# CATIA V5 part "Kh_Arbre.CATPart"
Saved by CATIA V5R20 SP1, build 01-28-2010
Part number: Arbre
Bounding box of the stored display mesh (mm): x -110 to 84, y -15 to 15, z -15 to 15
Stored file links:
  G:\Khaled_CFAO_2011\SIL\SIL_GR1\tmerino\Khaled\CAD_Thinkmotion\Kh_Arbre.CATPart
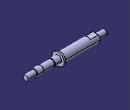
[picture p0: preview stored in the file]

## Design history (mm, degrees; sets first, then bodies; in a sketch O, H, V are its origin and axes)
Body1 (main body)
  Sketch1 on yz-plane, origin (0, 0, 0), H (0, 1, 0), V (0, 0, 1)
    circle A1 centre (0, 0) radius 15
    radius A1 = 15
  Pad1: profile Sketch1, direction (1, 0, 0), length 4
  Sketch2 on end face of Pad1, origin (4, 0, 0), H (0, 1, 0), V (0, 0, 1)
  Sketch3 on start face of Pad1, origin (0, 0, 0), H (0, -1, 0), V (0, 0, 1)
    circle A1 centre (0, 0) radius 11
    radius A1 = 11
  Pad2: profile Sketch3, direction (-1, 0, 0), length 88
  Sketch4 on end face of Pad2, origin (-88, 0, 0), H (0, -1, 0), V (0, 0, 1)
    circle A1 centre (0, 0) radius 6
    radius A1 = 6
  Pad3: profile Sketch4, direction (-1, 0, 0), length 22
  Sketch5 on zx-plane, origin (0, 0, 0), H (-1, 0, 0), V (0, 0, 1)
    line L1 (68, 20) -> (88, 20)
    line L2 (88, 20) -> (88, 8.5)
    line L3 (88, 8.5) -> (68, 8.5)
    line L4 (68, 8.5) -> (68, 20)
    reference projected line E1 (88, 11) -> (88, -11) from edge [face of Pad2 from Sketch3.A1 | end face of Pad2]
    reference projected line E2 through (0, 0) direction (1, 0) from axis of face of Pad2 from Sketch3.A1
    distance E1 L2 = 0
    distance L2 L4 = 20
    distance E2 L3 = 8.5
    horizontal: L1 H, L3 H
    vertical: L2 V, L4 V
  Pocket1: profile Sketch5, direction (0, 1, 0), length 22, opposite side length 22
  Sketch6 on end face of Pad1, origin (4, 0, 0), H (0, 1, 0), V (0, 0, 1)
    circle A1 centre (0, 0) radius 8.5
    radius A1 = 8.5
  Pad4: profile Sketch6, direction (1, 0, 0), length 16
  Sketch7 on end face of Pad4, origin (20, 0, 0), H (0, 1, 0), V (0, 0, 1)
    circle A1 centre (0, 0) radius 7.5
    radius A1 = 7.5
  Pad5: profile Sketch7, direction (1, 0, 0), length 26
  Sketch8 on end face of Pad5, origin (46, 0, 0), H (0, 1, 0), V (0, 0, 1)
    circle A1 centre (0, 0) radius 8.5
    radius A1 = 8.5
  Pad6: profile Sketch8, direction (1, 0, 0), length 16
  Sketch9 on end face of Pad6, origin (62, 0, 0), H (0, 1, 0), V (0, 0, 1)
    circle A1 centre (0, 0) radius 6
    radius A1 = 6
  Pad7: profile Sketch9, direction (1, 0, 0), length 22
  Chamfer1: length 1, angle 45, on edge [face of Pad4 from Sketch6.A1 | end face of Pad4]
  Chamfer2: length 1, angle 45, on edge [start face of Pad6 | face of Pad6 from Sketch8.A1]
  Fillet1: radius 2, on edge [start face of Pad1 | face of Pad2 from Sketch3.A1]
  Thread1: diameter 12, depth 10, pitch 1, on face of Pad3 from Sketch4.A1, from end face of Pad2
  Thread2: diameter 12, depth 10, pitch 1, on face of Pad7 from Sketch9.A1, from end face of Pad6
